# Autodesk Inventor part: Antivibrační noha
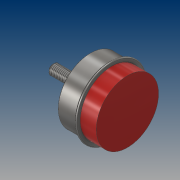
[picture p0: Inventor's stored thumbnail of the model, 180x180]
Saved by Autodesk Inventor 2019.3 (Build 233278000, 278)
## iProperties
Created: 2019-03
Part Number: Antivibrační noha
Material: Ocel, legovaná
Document SubType Name: Modeling
Designer: B-hon
Density: 7.73 g/cm^3
Appearance: Pololeštěná
Author: B-hon
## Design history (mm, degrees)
sketch "Náčrt1"
  geometry: L1 (0, 0)-(0, 29.5); L2 (0.5, 30)-(19.5, 30); L3 (20, 30.5)-(20, 33.2); L4 (18.634, 33.766)-(17.3, 32.432); L5 (-8.148, 0)-(38.635, 0); L6 (18.008, 31.725)-(18.146, 31.864); L7 (19, 31.51)-(19, 31.5); L8 (18.5, 31)-(-0.5, 31); L9 (-1, 30.5)-(-1, 0); L10 (18.008, 31.725)-(17.3, 32.432); L11 (-1, 0)-(0, 0); A1 r 0.8 centre (19.2, 33.2) between (20, 33.2) and (18.634, 33.766); A2 r 0.5 centre (-0.5, 30.5) between (-0.5, 31) and (-1, 30.5); A3 r 0.5 centre (0.5, 29.5) between (0.5, 30) and (0, 29.5); A4 r 0.5 centre (18.5, 31.51) between (19, 31.51) and (18.146, 31.864); A5 r 0.5 centre (18.5, 31.5) between (18.5, 31) and (19, 31.5); A6 r 0.5 centre (19.5, 30.5) between (19.5, 30) and (20, 30.5); 2 further points
  constraints: 22 end point, 12 point on circle, 12 tangent, 6 centre point, 5 perpendicular, 5 point on line, 4 equal radius, 1 collinear, 1 horizontal, 1 vertical, 2 other
  dimensions: "d1" = 60 diameter of L2 L5; "d2" = 20 distance of point (0, 30) point (20, 30); "d4" = 45 deg angle of L3 L4; "d5" = 1 distance between parallel lines of L2 L8; "d6" = 0.8 radius of A1; "d7" = 68 dimension on A1 L5; "d8" = 1 distance between parallel lines of L4 L6; "d9" = 0.5 radius of A2
revolve "Rotace1" sketch "Náčrt1" stored, may be unused: angle "d10" = 90 deg
sketch "Náčrt2"
  geometry: C1 r 30 at (0, 0) reference; 1 further point
extrude "Vysunutí1" join sketch "Náčrt2" distance "d11" = 35; taper "d12" = 0 deg
sketch "Náčrt3"
  geometry: C1 r 5 at (0, 0); 1 further point
  constraints: 1 centre point, 1 coincident
  dimensions: "d13" = 10 diameter of C1
extrude "Vysunutí2" join sketch "Náčrt3" distance "d14" = 36; taper "d15" = 0 deg
fillet "Zaoblení1" dims "d16" = 1.5
chamfer "Zkosení1" distance "d17" = 1.5; stored, may be unused: second distance "d18" = 2, angle "d19" = 45 deg
feature "Závit1" dims "d20" = 10, "d21" = 0
node "Těleso1"
